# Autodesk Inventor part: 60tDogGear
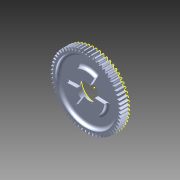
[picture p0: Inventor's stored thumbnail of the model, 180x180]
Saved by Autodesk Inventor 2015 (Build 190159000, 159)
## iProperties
Created: 2014-11
Part Number: 60tDogGear
Material: Generic
Document SubType Name: Modeling
Designer: Michael
Density: 1 g/cm^3
Appearance: Default
Title: 217-3420-STEP.STEP
Description: STEP AP214
Creation Date: 2013-12-09
Sending System: SolidWorks 2013
Preprocessor: SwSTEP 2.0
Author: Michael
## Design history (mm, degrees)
node "60tDogGear1"
sketch "Sketch1"
  geometry: C1 r 14.288 at (35.017, 14.587) reference; A1 r 39.37 centre (35.017, 14.587) between (-2.259, 1.918) and (-1.87, 0.826) reference; A2 r 39.37 centre (35.017, 14.587) between (-0.731, -1.909) and (-0.229, -2.955) reference; A3 r 39.37 centre (35.017, 14.587) between (1.19, -5.555) and (1.798, -6.543) reference; A4 r 39.37 centre (35.017, 14.587) between (3.48, -8.981) and (4.188, -9.899) reference; A5 r 39.37 centre (35.017, 14.587) between (6.117, -12.148) and (6.917, -12.988) reference; A6 r 39.37 centre (35.017, 14.587) between (9.07, -15.022) and (9.953, -15.774) reference; A7 r 39.37 centre (35.017, 14.587) between (12.307, -17.572) and (13.264, -18.227) reference; A8 r 39.37 centre (35.017, 14.587) between (15.793, -19.77) and (16.813, -20.321) reference; A9 r 39.37 centre (35.017, 14.587) between (19.489, -21.591) and (20.562, -22.033) reference; A10 r 39.37 centre (35.017, 14.587) between (23.356, -23.016) and (24.469, -23.343) reference; A11 r 39.37 centre (35.017, 14.587) between (27.351, -24.029) and (28.492, -24.238) reference; A12 r 39.37 centre (35.017, 14.587) between (31.429, -24.619) and (32.586, -24.708) reference; A13 r 39.37 centre (35.017, 14.587) between (35.547, -24.779) and (36.706, -24.746) reference; A14 r 39.37 centre (35.017, 14.587) between (39.659, -24.508) and (40.809, -24.354) reference; A15 r 39.37 centre (35.017, 14.587) between (43.72, -23.809) and (44.847, -23.536) reference; A16 r 39.37 centre (35.017, 14.587) between (47.686, -22.689) and (48.778, -22.299) reference; A17 r 39.37 centre (35.017, 14.587) between (51.513, -21.16) and (52.559, -20.659) reference; A18 r 39.37 centre (35.017, 14.587) between (55.159, -19.24) and (56.147, -18.632) reference; A19 r 39.37 centre (35.017, 14.587) between (58.585, -16.949) and (59.503, -16.241) reference; A20 r 39.37 centre (35.017, 14.587) between (61.752, -14.313) and (62.592, -13.513) reference; A21 r 39.37 centre (35.017, 14.587) between (64.627, -11.36) and (65.378, -10.476) reference; A22 r 39.37 centre (35.017, 14.587) between (67.177, -8.123) and (67.832, -7.166) reference; A23 r 39.37 centre (35.017, 14.587) between (69.374, -4.637) and (69.926, -3.616) reference; A24 r 39.37 centre (35.017, 14.587) between (71.195, -0.94) and (71.637, 0.132) reference; A25 r 39.37 centre (35.017, 14.587) between (72.62, 2.927) and (72.947, 4.039) reference; A26 r 39.37 centre (35.017, 14.587) between (73.633, 6.921) and (73.842, 8.062) reference; A27 r 39.37 centre (35.017, 14.587) between (74.223, 11) and (74.312, 12.156) reference; A28 r 39.37 centre (35.017, 14.587) between (74.383, 15.118) and (74.35, 16.277) reference; A29 r 39.37 centre (35.017, 14.587) between (74.112, 19.23) and (73.958, 20.379) reference; A30 r 39.37 centre (35.017, 14.587) between (73.413, 23.291) and (73.14, 24.418) reference; A31 r 39.37 centre (35.017, 14.587) between (72.293, 27.257) and (71.903, 28.349) reference; A32 r 39.37 centre (35.017, 14.587) between (70.764, 31.084) and (70.263, 32.129) reference; A33 r 39.37 centre (35.017, 14.587) between (68.844, 34.73) and (68.236, 35.717) reference; A34 r 39.37 centre (35.017, 14.587) between (66.553, 38.155) and (65.845, 39.074) reference; A35 r 39.37 centre (35.017, 14.587) between (63.917, 41.323) and (63.117, 42.162) reference; A36 r 39.37 centre (35.017, 14.587) between (60.964, 44.197) and (60.081, 44.949) reference; A37 r 39.37 centre (35.017, 14.587) between (57.727, 46.747) and (56.77, 47.402) reference; A38 r 39.37 centre (35.017, 14.587) between (54.241, 48.945) and (53.22, 49.496) reference; A39 r 39.37 centre (35.017, 14.587) between (50.544, 50.766) and (49.472, 51.208) reference; A40 r 39.37 centre (35.017, 14.587) between (46.677, 52.191) and (45.565, 52.518) reference; A41 r 39.37 centre (35.017, 14.587) between (42.683, 53.204) and (41.542, 53.413) reference; A42 r 39.37 centre (35.017, 14.587) between (38.604, 53.794) and (37.448, 53.882) reference; A43 r 39.37 centre (35.017, 14.587) between (34.486, 53.954) and (33.327, 53.921) reference; A44 r 39.37 centre (35.017, 14.587) between (30.374, 53.683) and (29.225, 53.529) reference; A45 r 39.37 centre (35.017, 14.587) between (26.313, 52.983) and (25.186, 52.71) reference; A46 r 39.37 centre (35.017, 14.587) between (22.348, 51.863) and (21.255, 51.474) reference; A47 r 39.37 centre (35.017, 14.587) between (18.521, 50.335) and (17.475, 49.833) reference; A48 r 39.37 centre (35.017, 14.587) between (14.874, 48.415) and (13.887, 47.807) reference; A49 r 39.37 centre (35.017, 14.587) between (11.449, 46.124) and (10.53, 45.416) reference; A50 r 39.37 centre (35.017, 14.587) between (8.281, 43.487) and (7.442, 42.687) reference; A51 r 39.37 centre (35.017, 14.587) between (5.407, 40.535) and (4.656, 39.651) reference; A52 r 39.37 centre (35.017, 14.587) between (2.857, 37.297) and (2.202, 36.34) reference; A53 r 39.37 centre (35.017, 14.587) between (0.659, 33.811) and (0.108, 32.791) reference; A54 r 39.37 centre (35.017, 14.587) between (-1.162, 30.115) and (-1.604, 29.042) reference; A55 r 39.37 centre (35.017, 14.587) between (-2.587, 26.248) and (-2.914, 25.135) reference; A56 r 39.37 centre (35.017, 14.587) between (-3.6, 22.253) and (-3.809, 21.113) reference; A57 r 39.37 centre (35.017, 14.587) between (-4.189, 18.175) and (-4.278, 17.018) reference; A58 r 39.37 centre (35.017, 14.587) between (-4.35, 14.057) and (-4.317, 12.898) reference; A59 r 39.37 centre (35.017, 14.587) between (-4.079, 9.945) and (-3.925, 8.795) reference; A60 r 39.37 centre (35.017, 14.587) between (-3.379, 5.884) and (-3.106, 4.757) reference; A61 r 0.558 centre (35.656, 51.658) between (35.098, 51.672) and (35.72, 51.104); A62 r 0.532 centre (32.307, 51.544) between (32.359, 51.014) and (32.839, 51.551)
  constraints: 4 point on circle, 2 centre point, 65 other
workplane "Work Plane1"
node "BackBore"
node "Base1"
